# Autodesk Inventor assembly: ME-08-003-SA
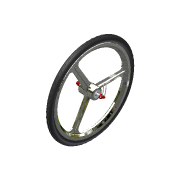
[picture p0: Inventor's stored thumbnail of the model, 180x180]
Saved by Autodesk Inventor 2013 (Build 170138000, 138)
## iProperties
Shininess: 20.0
Length Units: 11269
Angle Units: 11279
Time Units: 11290
Mass Units: 11283
Length Display Precision: 3
Angle Display Precision: 2
Created: 2001-04
Part Number: ME-08-003-SA
Document SubType Name: Baugruppe
Designer: dl
Density: 0.0
Volumn: 0.0
Area: 0.0
PropertySet Name: Model Information
Control State: 0
Master: False
Checked Out: False
Author: dl
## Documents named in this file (8)
- C:\Webworld\Webworld2014\ATC2013\Assemblies\ATC-Baby Carriage\3-FRONT WHEEL\ME-08-003-SA.iam
- C:\Webworld\Webworld2014\ATC2013\Assemblies\ATC-Baby Carriage\3-FRONT WHEEL\Quick-action_lock_nut vst.iam
- C:\Webworld\Webworld2014\ATC2013\Assemblies\ATC-Baby Carriage\3-FRONT WHEEL\Front_wheel_axis 24.ipt
- C:\Webworld\Webworld2014\ATC2013\Assemblies\ATC-Baby Carriage\3-FRONT WHEEL\Circlip - DIN 471 - 15 X 1.ipt
- C:\Webworld\Webworld2014\ATC2013\Assemblies\ATC-Baby Carriage\3-FRONT WHEEL\Rim_carbon.ipt
- C:\Webworld\Webworld2014\ATC2013\Assemblies\ATC-Baby Carriage\3-FRONT WHEEL\Tyre.ipt
- C:\Webworld\Webworld2014\ATC2013\Assemblies\ATC-Baby Carriage\3-FRONT WHEEL\DIN 625 T1 - 6201 - 12 x 32 x 10.ipt
- C:\Webworld\Webworld2014\ATC2013\Assemblies\ATC-Baby Carriage\3-FRONT WHEEL\Bearing_shell.ipt
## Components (9 placed, 7 different names)
1. Quick-action_lock_nut vst:1 [sub-assembly] — Mate:1, Mate:2
2. Front_wheel_axis 24:1 — Mate:1, Mate:2
3. Tyre:1
4. Circlip - DIN 471 - 15 X 1:1
5. Circlip - DIN 471 - 15 X 1:2
6. DIN 625 T1 - 6201 - 12 x 32 x 10:1 — Insert:1
7. DIN 625 T1 - 6201 - 12 x 32 x 10:2
8. Rim_carbon:1 — Insert:2
9. Bearing_shell:1 — Insert:1, Insert:2
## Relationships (4: Mate 2, Insert 2)
- Mate:1: Quick-action_lock_nut vst:1 ↔ Front_wheel_axis 24:1
- Mate:2: Quick-action_lock_nut vst:1 ↔ Front_wheel_axis 24:1
- Insert:1: DIN 625 T1 - 6201 - 12 x 32 x 10:1 ↔ Bearing_shell:1
- Insert:2: Rim_carbon:1 ↔ Bearing_shell:1
